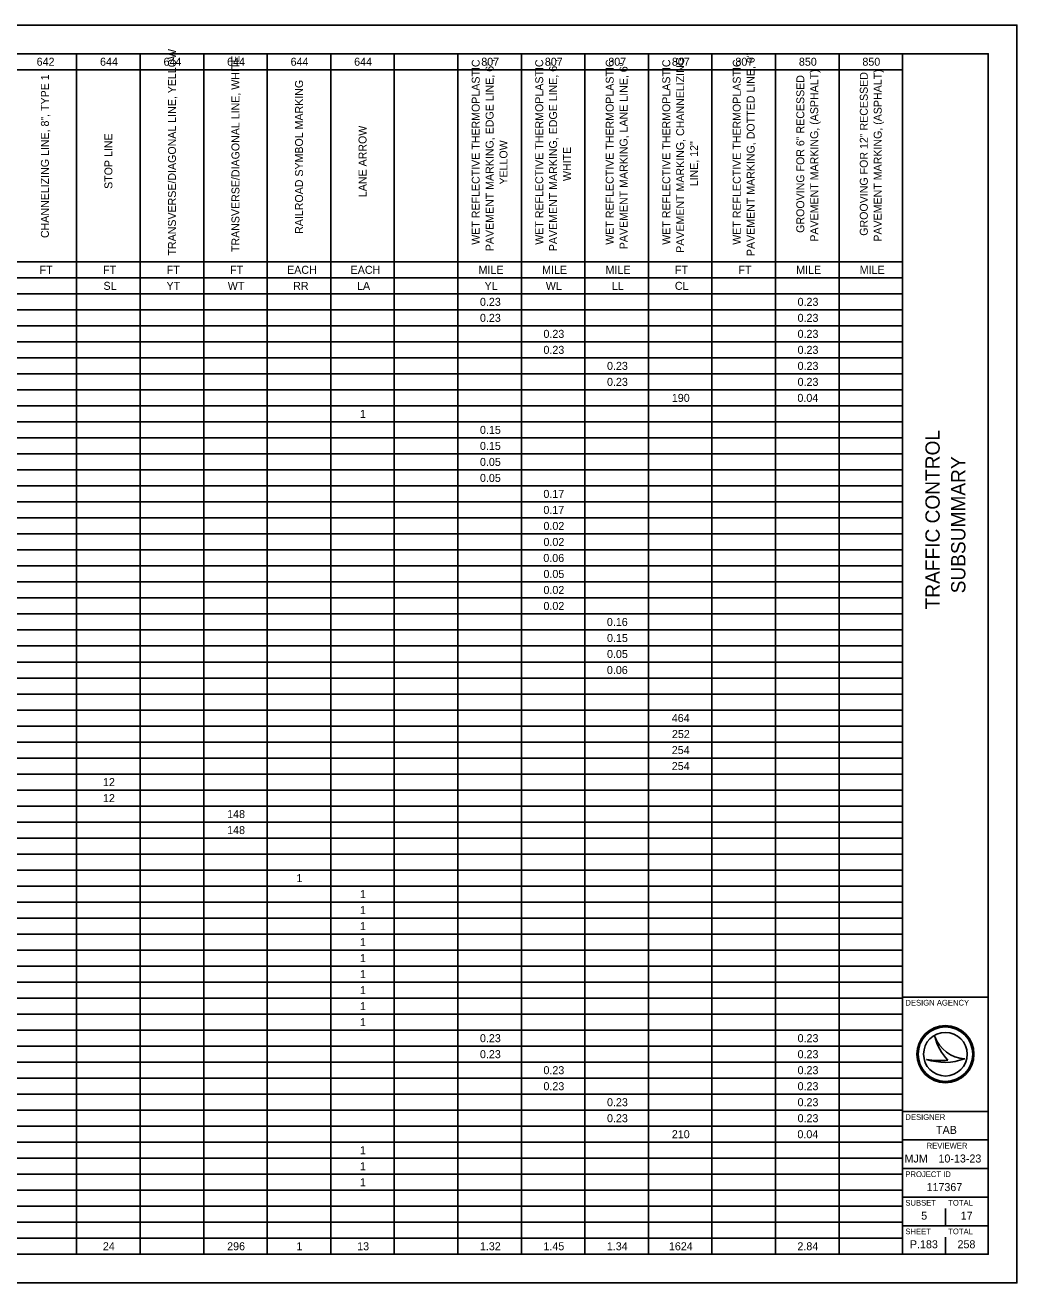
# Model space of a CAD drawing. Extents: x 0 to 34, y 0 to 22.
# Drawn here: x 16.65 to 34, y 0 to 22 of the extents above; entities that cross this region are included whole.
import ezdxf

# ---------------------------------------------------------------- set-up
doc = ezdxf.new("R2010")
doc.units = 0
for name, color, linetype in [('SH_Border', 7, 'Continuous'), ('SH_Cut_Line', 7, 'Continuous'), ('SH_Data', 7, 'Continuous'), ('SH_Text', 7, 'Continuous')]:
    doc.layers.add(name, color=color, linetype=linetype)

msp = doc.modelspace()

# ---------------------------------------------------------------- linework, layer by layer
at = {"layer": 'SH_Border'}
for p, q in [((32, 0.5), (32, 21.5)), ((32, 5), (33.5, 5)), ((32, 3), (33.5, 3)), ((32, 2.5), (33.5, 2.5)), ((32, 2), (33.5, 2)), ((32, 1.5), (33.5, 1.5)), ((32, 1), (33.5, 1))]:
    msp.add_line(p, q, dxfattribs=at)
msp.add_lwpolyline([(1.5, 21.5), (33.5, 21.5), (33.5, 0.5), (1.5, 0.5)], close=True, dxfattribs=at)
at = {"layer": 'SH_Cut_Line'}
msp.add_lwpolyline([(0, 0), (34, 0), (34, 22), (0, 22)], close=True, dxfattribs=at)
at = {"layer": 'SH_Data'}
for p, q in [((32.567, 4.31), (32.567, 4.31)), ((32.75, 4), (32.75, 4)), ((32.417, 3.91), (32.417, 3.91)), ((33.087, 3.919), (33.087, 3.919)), ((32.75, 1), (32.75, 1.3)), ((32.375, 0.675), (32.375, 0.675)), ((32.75, 0.5), (32.75, 0.8))]:
    msp.add_line(p, q, dxfattribs=at)
for radius in [0.5, 0.477, 0.477, 0.382]:
    msp.add_circle((32.75, 4), radius, dxfattribs=at)
for centre, radius, start, end in [((33.116, 4.498), 0.58, 198.9257, 198.9319), ((33.347, 4.47), 0.796, 191.6379, 191.6421), ((33.116, 4.498), 0.58, 198.9319, 267.1657), ((33.347, 4.47), 0.796, 191.6421, 226.0947), ((32.739, 4.87), 1.013, 251.4576, 290.0832), ((32.648, 5.154), 1.266, 259.4964, 259.4995), ((32.739, 4.87), 1.013, 251.4527, 251.4576), ((32.648, 5.154), 1.266, 259.4995, 276.6672)]:
    msp.add_arc(centre, radius, start, end, dxfattribs=at)
at = {"layer": 'SH_Text'}
for p, q in [((1.5, 21.5), (32, 21.5)), ((17.551, 21.5), (17.551, 0.5)), ((18.662, 21.5), (18.662, 0.5)), ((19.774, 21.5), (19.774, 0.5)), ((20.885, 21.5), (20.885, 0.5)), ((21.997, 21.5), (21.997, 0.5)), ((23.108, 21.5), (23.108, 0.5)), ((24.22, 21.5), (24.22, 0.5)), ((25.331, 21.5), (25.331, 0.5)), ((26.443, 21.5), (26.443, 0.5)), ((27.554, 21.5), (27.554, 0.5)), ((28.666, 21.5), (28.666, 0.5)), ((29.777, 21.5), (29.777, 0.5)), ((30.889, 21.5), (30.889, 0.5)), ((32, 21.5), (32, 0.5)), ((8.659, 21.22), (32, 21.22)), ((8.659, 17.86), (32, 17.86)), ((1.5, 17.58), (32, 17.58)), ((1.5, 17.3), (32, 17.3)), ((1.5, 17.02), (32, 17.02)), ((1.5, 16.74), (32, 16.74)), ((1.5, 16.46), (32, 16.46)), ((1.5, 16.18), (32, 16.18)), ((1.5, 15.9), (32, 15.9)), ((1.5, 15.62), (32, 15.62)), ((1.5, 15.34), (32, 15.34)), ((1.5, 15.06), (32, 15.06)), ((1.5, 14.78), (32, 14.78)), ((1.5, 14.5), (32, 14.5)), ((1.5, 14.22), (32, 14.22)), ((1.5, 13.94), (32, 13.94)), ((1.5, 13.66), (32, 13.66)), ((1.5, 13.38), (32, 13.38)), ((1.5, 13.1), (32, 13.1)), ((1.5, 12.82), (32, 12.82)), ((1.5, 12.54), (32, 12.54)), ((1.5, 12.26), (32, 12.26)), ((1.5, 11.98), (32, 11.98)), ((1.5, 11.7), (32, 11.7)), ((1.5, 11.42), (32, 11.42)), ((1.5, 11.14), (32, 11.14)), ((1.5, 10.86), (32, 10.86)), ((1.5, 10.58), (32, 10.58)), ((1.5, 10.3), (32, 10.3)), ((1.5, 10.02), (32, 10.02)), ((1.5, 9.74), (32, 9.74)), ((1.5, 9.46), (32, 9.46)), ((1.5, 9.18), (32, 9.18)), ((1.5, 8.9), (32, 8.9)), ((1.5, 8.62), (32, 8.62)), ((1.5, 8.34), (32, 8.34)), ((1.5, 8.06), (32, 8.06)), ((1.5, 7.78), (32, 7.78)), ((1.5, 7.5), (32, 7.5)), ((1.5, 7.22), (32, 7.22)), ((1.5, 6.94), (32, 6.94)), ((1.5, 6.66), (32, 6.66)), ((1.5, 6.38), (32, 6.38)), ((1.5, 6.1), (32, 6.1)), ((1.5, 5.82), (32, 5.82)), ((1.5, 5.54), (32, 5.54)), ((1.5, 5.26), (32, 5.26)), ((1.5, 4.98), (32, 4.98)), ((1.5, 4.7), (32, 4.7)), ((1.5, 4.42), (32, 4.42)), ((1.5, 4.14), (32, 4.14)), ((1.5, 3.86), (32, 3.86)), ((1.5, 3.58), (32, 3.58)), ((1.5, 3.3), (32, 3.3)), ((1.5, 3.02), (32, 3.02)), ((1.5, 2.74), (32, 2.74)), ((1.5, 2.46), (32, 2.46)), ((1.5, 2.18), (32, 2.18)), ((1.5, 1.9), (32, 1.9)), ((1.5, 1.62), (32, 1.62)), ((1.5, 1.34), (32, 1.34)), ((1.5, 1.06), (32, 1.06)), ((1.5, 0.78), (32, 0.78)), ((1.5, 0.5), (32, 0.5))]:
    msp.add_line(p, q, dxfattribs=at)

# ---------------------------------------------------------------- texts
at = {"layer": 'SH_Data'}
for s, p in [('TRAFFIC CONTROL', (32.65, 11.78)), ('SUBSUMMARY', (33.1, 12.061))]:
    msp.add_text(s, height=0.25, rotation=90, dxfattribs=at).set_placement(p)
for s, height, p in [('DESIGN AGENCY', 0.1, (32.05, 4.85)), ('DESIGNER', 0.1, (32.05, 2.85)), ('TAB', 0.14, (32.586, 2.605)), ('REVIEWER', 0.1, (32.422, 2.35)), ('MJM', 0.14, (32.035, 2.105)), ('10-13-23', 0.14, (32.629, 2.105)), ('PROJECT ID', 0.1, (32.05, 1.85)), ('117367', 0.14, (32.42, 1.605)), ('SUBSET', 0.1, (32.05, 1.35)), ('TOTAL', 0.1, (32.8, 1.35)), ('5', 0.14, (32.326, 1.105)), ('17', 0.14, (33.018, 1.105)), ('SHEET', 0.1, (32.05, 0.85)), ('TOTAL', 0.1, (32.8, 0.85)), ('P.183', 0.14, (32.129, 0.605)), ('258', 0.14, (32.962, 0.605))]:
    msp.add_text(s, height=height, dxfattribs=at).set_placement(p)
at = {"layer": 'SH_Text'}
for s, height, p in [('TRANSVERSE/DIAGONAL LINE, YELLOW', 0.13893, (19.288, 17.97)), ('TRANSVERSE/DIAGONAL LINE, WHITE', 0.13893, (20.399, 18.031)), ('WET REFLECTIVE THERMOPLASTIC ', 0.13893, (24.602, 18.159)), ('PAVEMENT MARKING, EDGE LINE, 6", ', 0.13893, (24.845, 18.046)), ('WET REFLECTIVE THERMOPLASTIC ', 0.13893, (25.713, 18.159)), ('PAVEMENT MARKING, EDGE LINE, 6", ', 0.13893, (25.956, 18.046)), ('WET REFLECTIVE THERMOPLASTIC ', 0.13893, (26.946, 18.159)), ('WET REFLECTIVE THERMOPLASTIC ', 0.13893, (27.936, 18.159)), ('PAVEMENT MARKING, CHANNELIZING ', 0.13893, (28.179, 18.017)), ('WET REFLECTIVE THERMOPLASTIC ', 0.13893, (29.169, 18.159)), ('PAVEMENT MARKING, DOTTED LINE, 6"', 0.13893, (29.412, 17.96)), ('CHANNELIZING LINE, 8", TYPE 1', 0.13893, (17.065, 18.276)), ('PAVEMENT MARKING, LANE LINE, 6"', 0.13893, (27.189, 18.08)), ('PAVEMENT MARKING, (ASPHALT)', 0.13893, (30.524, 18.213)), ('GROOVING FOR 12" RECESSED ', 0.13893, (31.392, 18.316)), ('PAVEMENT MARKING, (ASPHALT)', 0.13893, (31.635, 18.213)), ('RAILROAD SYMBOL MARKING', 0.13893, (21.511, 18.349)), ('GROOVING FOR 6" RECESSED ', 0.13893, (30.281, 18.367)), ('LANE ARROW', 0.1389, (22.622, 18.992)), ('STOP LINE', 0.1389, (18.176, 19.136)), ('YELLOW', 0.1389, (25.088, 19.212)), ('WHITE', 0.1389, (26.2, 19.273)), ('LINE, 12"', 0.1389, (28.422, 19.181))]:
    msp.add_text(s, height=height, rotation=90, dxfattribs=at).set_placement(p)
for s, p in [('642', (16.851, 21.29)), ('644', (17.96, 21.29)), ('644', (19.071, 21.29)), ('644', (20.183, 21.29)), ('644', (21.294, 21.29)), ('644', (22.406, 21.29)), ('807', (24.63, 21.29)), ('807', (25.742, 21.29)), ('807', (26.853, 21.29)), ('807', (27.965, 21.29)), ('807', (29.076, 21.29)), ('850', (30.187, 21.29)), ('850', (31.298, 21.29)), ('FT', (16.903, 17.65)), ('FT', (18.014, 17.65)), ('FT', (19.126, 17.65)), ('FT', (20.237, 17.65)), ('EACH', (21.232, 17.65)), ('EACH', (22.344, 17.65)), ('MILE', (24.582, 17.65)), ('MILE', (25.694, 17.65)), ('MILE', (26.805, 17.65)), ('FT', (28.017, 17.65)), ('FT', (29.129, 17.65)), ('MILE', (30.139, 17.65)), ('MILE', (31.251, 17.65)), ('SL', (18.021, 17.37)), ('YT', (19.123, 17.37)), ('WT', (20.195, 17.37)), ('RR', (21.338, 17.37)), ('LA', (22.456, 17.37)), ('YL', (24.687, 17.37)), ('WL', (25.759, 17.37)), ('LL', (26.916, 17.37)), ('CL', (28.017, 17.37)), ('0.23', (24.607, 17.09)), ('0.23', (30.164, 17.09)), ('0.23', (24.607, 16.81)), ('0.23', (30.164, 16.81)), ('0.23', (25.718, 16.53)), ('0.23', (30.164, 16.53)), ('0.23', (25.718, 16.25)), ('0.23', (30.164, 16.25)), ('0.23', (26.83, 15.97)), ('0.23', (30.164, 15.97)), ('0.23', (26.83, 15.69)), ('0.23', (30.164, 15.69)), ('190', (27.964, 15.41)), ('0.04', (30.161, 15.41)), ('1', (22.508, 15.13)), ('0.15', (24.607, 14.85)), ('0.15', (24.607, 14.57)), ('0.05', (24.607, 14.29)), ('0.05', (24.607, 14.01)), ('0.17', (25.717, 13.73)), ('0.17', (25.717, 13.45)), ('0.02', (25.718, 13.17)), ('0.02', (25.718, 12.89)), ('0.06', (25.716, 12.61)), ('0.05', (25.718, 12.33)), ('0.02', (25.718, 12.05)), ('0.02', (25.718, 11.77)), ('0.16', (26.828, 11.49)), ('0.15', (26.83, 11.21)), ('0.05', (26.83, 10.93)), ('0.06', (26.828, 10.65)), ('464', (27.963, 9.81)), ('252', (27.966, 9.53)), ('254', (27.963, 9.25)), ('254', (27.963, 8.97)), ('12', (18.012, 8.69)), ('12', (18.012, 8.41)), ('148', (20.184, 8.13)), ('148', (20.184, 7.85)), ('1', (21.396, 7.01)), ('1', (22.508, 6.73)), ('1', (22.508, 6.45)), ('1', (22.508, 6.17)), ('1', (22.508, 5.89)), ('1', (22.508, 5.61)), ('1', (22.508, 5.33)), ('1', (22.508, 5.05)), ('1', (22.508, 4.77)), ('1', (22.508, 4.49)), ('0.23', (24.607, 4.21)), ('0.23', (30.164, 4.21)), ('0.23', (24.607, 3.93)), ('0.23', (30.164, 3.93)), ('0.23', (25.718, 3.65)), ('0.23', (30.164, 3.65)), ('0.23', (25.718, 3.37)), ('0.23', (30.164, 3.37)), ('0.23', (26.83, 3.09)), ('0.23', (30.164, 3.09)), ('0.23', (26.83, 2.81)), ('0.23', (30.164, 2.81)), ('210', (27.964, 2.53)), ('0.04', (30.161, 2.53)), ('1', (22.508, 2.25)), ('1', (22.508, 1.97)), ('1', (22.508, 1.69)), ('24', (18.01, 0.57)), ('296', (20.184, 0.57)), ('1', (21.396, 0.57)), ('13', (22.459, 0.57)), ('1.32', (24.606, 0.57)), ('1.45', (25.718, 0.57)), ('1.34', (26.827, 0.57)), ('1624', (27.913, 0.57)), ('2.84', (30.161, 0.57))]:
    msp.add_text(s, height=0.14, dxfattribs=at).set_placement(p)

doc.saveas('drawing.dxf')
